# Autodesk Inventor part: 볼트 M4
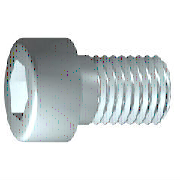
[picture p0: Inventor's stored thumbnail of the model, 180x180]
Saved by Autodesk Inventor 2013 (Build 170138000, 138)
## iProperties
IsCustomPart: 0
Created: 2012-02
Part Number: 볼트 M4
Material: 스테인리스강
Description: 6각 소켓 머리 캡 나사
Document SubType Name: Modeling
Standard: ISO 4762
Designer: mduedu
Standard Revision: Fourth edition 2004-03-01
Standards Organization: ISO
Language: ko-KR
Size Designation: M4 x 10
Categories: <MemberInstance><Categories><Category DisplayName="조임쇠" InternalName="e4da775c-781d-43d5-af7c-5136215cf5a6" Mnemonic="FSTN"><Category DisplayName="볼트" InternalN
Density: 7.75 g/cm^3
Author: mduedu
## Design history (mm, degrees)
sketch "스케치1"
  geometry: L1 (-1, 0)-(10, 0); L2 (10, 0)-(10, 2); L3 (10, 2)-(1.75, 2); L4 (1.75, 2)-(1.32, 2); L5 (1.32, 2)-(0, 2); L6 (0, 2)-(0, 3.5); L7 (0, 3.5)-(-4, 3.5); L8 (-4, 3.5)-(-4, 1.732); L9 (-4, 1.732)-(-2, 1.732); L10 (-2, 1.732)-(-1, 0); L11 (-6.8, 0)-(12.8, 0) reference; L12 (0, -0.7)-(0, 4.2) reference; L13 (1.75, 2)-(0, 2)
  constraints: 22 end point, 6 parallel, 2 collinear, 2 perpendicular, 1 horizontal, 1 point on line
  dimensions: "d1" = 8.25 distance from line of L3.end L2 (= GEL); "d2" = 0.42952 distance of L4.end L3.end (computed from GAL); "d3" = 4 distance between parallel lines of L8 L6 (= KOH); "d4" = 2 distance of L8.end L9.end (= INTI); "d5" = 60 deg angle of L10 L1; "d6" = 4 diameter of L3 L1 (= GD); "d7" = 4 diameter of L5 L1 (= BDM); "d8" = 3.4641 diameter of L9 L1 (= 1.1547 x SW); "d9" = 7 diameter of L7 L1 (= KOD); "d26" = 10 distance between parallel lines of L12 L2 (= NLG)
revolve "본체" sketch "스케치1" stored, may be unused: angle "d10" = 90 deg
sketch "스케치2"
  geometry: L1 (0, -4.9)-(0, 4.9) reference; L2 (-4.9, 0)-(4.9, 0) reference; L3 (1.732, 0)-(0.866, -1.5); L4 (0.866, -1.5)-(-0.866, -1.5); L5 (-0.866, -1.5)-(-1.732, 0); L6 (-1.732, 0)-(-0.866, 1.5); L7 (-0.866, 1.5)-(0.866, 1.5); L8 (0.866, 1.5)-(1.732, 0); 2 further points
  constraints: 12 end point, 1 coincident, 1 horizontal alignment, 1 point on line, 12 other
extrude "슬롯" join sketch "스케치2" stored distance "d11" = 10; taper "d12" = 0 deg
workplane "Work Plane1"
fillet "Fillet2" dims "d30" = 0.1 (= R)
body "Solid1"
fillet "모깎기1" dims "d17" = 0.4 (= RR)
feature "스레드" dims "d13" = 8.25 (= GEL), "d14" = 0
chamfer "모따기1" distance "d15" = 0.42941 (= -0.5 x SPD + 0.5 x GD); stored, may be unused: second distance "d16" = 0.42941 (= GUL), angle "d27" = 45 deg
other parameters: "GD" = 4 [user parameter; used in 2 equation terms], "NLG" = 10 [user parameter; used in 1 equation term], "GEL" = 8.25 [user parameter; used in 2 equation terms], "KOD" = 7 [user parameter; used in 1 equation term], "KOH" = 4 [user parameter; used in 1 equation term], "INTI" = 2 [user parameter; used in 1 equation term], "GAL" = 0.42941 (= 0.61345 x PTC) [user parameter; used in 1 equation term], "GUL" = 0.42941 (= 0.61345 x PTC) [user parameter; used in 1 equation term], "BDM" = 4 (= NND) [user parameter; used in 1 equation term], "SW" = 3 [user parameter; used in 2 equation terms], "RR" = 0.4 [user parameter; used in 1 equation term], "SPD" = 3.14117 (= NND - 1.2269 x PTC) [user parameter; used in 1 equation term], "d19" = 0, "d28" = 0, "d29" = 0, "R" = 0.1 [user parameter; used in 1 equation term], "TOA" = 30 deg [user parameter], "GD1" = 3.14117 (= THREADDIA - 1.2269 x PTC) [user parameter], "THREADDIA" = 4 [user parameter; used in 1 equation term], "FAWI" = 45 deg [user parameter], "TPU" = 14.28571 (computed from PTC) [user parameter], "PTC" = 0.7 [user parameter; used in 5 equation terms], "NND" = 4 [user parameter; used in 2 equation terms], "E0" = 3.465 (= 1.155 x SW) [user parameter]
